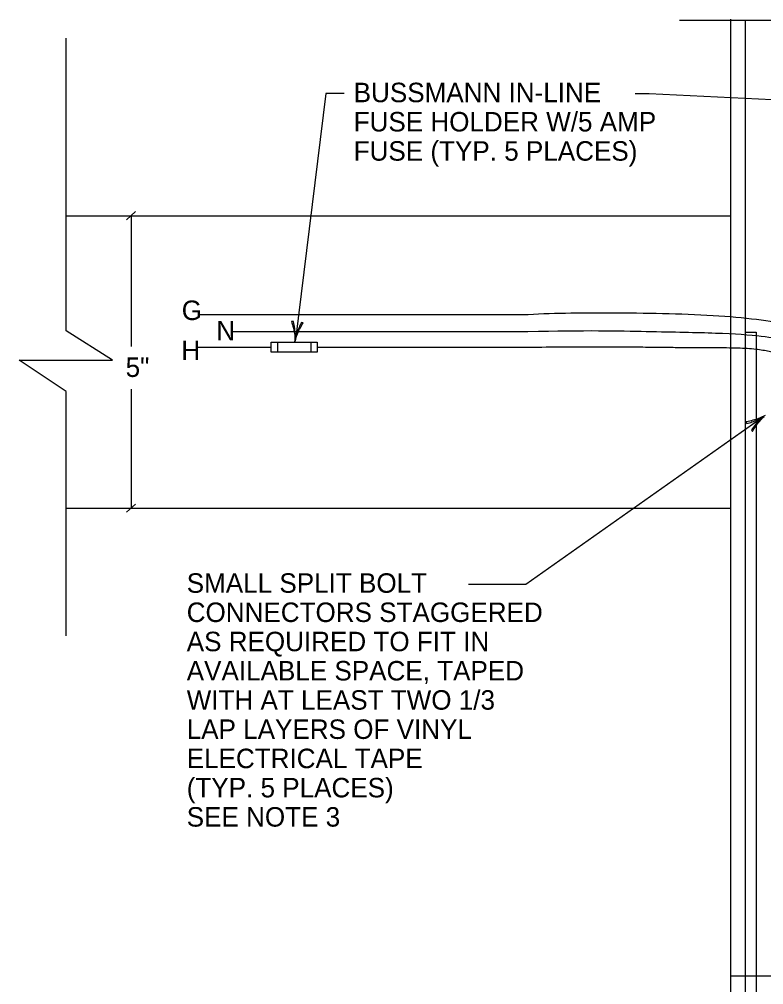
# Model space of a CAD drawing. Extents: x 10099 to 10284, y 10005 to 10185.
# Drawn here: x 10123.06 to 10148.54, y 10150.04 to 10183.07 of the extents above; entities that cross this region are included whole.
import ezdxf

# ---------------------------------------------------------------- set-up
doc = ezdxf.new("R2010")
doc.units = 0
doc.layers.add('Level 46', color=7, linetype='Continuous')
doc.layers.add('Level 5', color=7, linetype='Continuous')

msp = doc.modelspace()

# ---------------------------------------------------------------- linework, layer by layer
at = {"layer": 'Level 46'}
for p, q in [((10150.41, 10183.028), (10145.651, 10183.028)), ((10147.404, 10183.071), (10147.404, 10122.109)), ((10147.904, 10183.049), (10147.904, 10120.1)), ((10124.661, 10172.41), (10124.661, 10182.42)), ((10133.557, 10180.531), (10132.513, 10172.1)), ((10134.175, 10180.531), (10133.557, 10180.531)), ((10144.144, 10180.535), (10144.614, 10180.535)), ((10144.614, 10180.535), (10149.762, 10180.283)), ((10124.661, 10176.35), (10147.404, 10176.35)), ((10127.042, 10176.49), (10126.734, 10176.212)), ((10126.888, 10176.353), (10126.888, 10171.872)), ((10126.248, 10171.409), (10124.661, 10172.41)), ((10147.904, 10172.363), (10148.279, 10172.363)), ((10148.279, 10172.363), (10148.279, 10132.35)), ((10124.661, 10170.341), (10123.061, 10171.409)), ((10123.061, 10171.409), (10126.248, 10171.409)), ((10124.661, 10161.98), (10124.661, 10170.341)), ((10126.888, 10170.416), (10126.888, 10166.35)), ((10140.399, 10163.748), (10148.537, 10169.495)), ((10124.661, 10166.35), (10147.404, 10166.35)), ((10127.042, 10166.487), (10126.734, 10166.209)), ((10138.438, 10163.748), (10140.399, 10163.748)), ((10147.404, 10150.35), (10155.404, 10150.35))]:
    msp.add_line(p, q, dxfattribs=at)
for points in [[(10132.496, 10172.042), (10132.513, 10172.1), (10132.529, 10172.156), (10132.55, 10172.23), (10132.581, 10172.305), (10132.607, 10172.369), (10132.63, 10172.425), (10132.654, 10172.47), (10132.681, 10172.52), (10132.706, 10172.566), (10132.732, 10172.614), (10132.758, 10172.655), (10132.779, 10172.687), (10132.713, 10172.696), (10132.691, 10172.655), (10132.671, 10172.615), (10132.653, 10172.572), (10132.635, 10172.53), (10132.613, 10172.477), (10132.595, 10172.436), (10132.577, 10172.378), (10132.561, 10172.328), (10132.544, 10172.272), (10132.531, 10172.219), (10132.521, 10172.171), (10132.513, 10172.132), (10132.505, 10172.091), (10132.496, 10172.042), (10132.5, 10172.105), (10132.502, 10172.167), (10132.506, 10172.249), (10132.502, 10172.324), (10132.499, 10172.379), (10132.496, 10172.437), (10132.489, 10172.492), (10132.478, 10172.563), (10132.47, 10172.614), (10132.459, 10172.666), (10132.445, 10172.729), (10132.377, 10172.737), (10132.394, 10172.69), (10132.415, 10172.622), (10132.427, 10172.571), (10132.444, 10172.504), (10132.46, 10172.438), (10132.468, 10172.382), (10132.478, 10172.313), (10132.486, 10172.263), (10132.489, 10172.208), (10132.491, 10172.154), (10132.494, 10172.098), (10132.496, 10172.042)], [(10148.591, 10169.521), (10148.537, 10169.495), (10148.484, 10169.469), (10148.415, 10169.435), (10148.339, 10169.407), (10148.274, 10169.384), (10148.217, 10169.363), (10148.167, 10169.351), (10148.113, 10169.337), (10148.062, 10169.324), (10148.009, 10169.311), (10147.961, 10169.303), (10147.923, 10169.297), (10147.961, 10169.242), (10148.006, 10169.254), (10148.049, 10169.266), (10148.093, 10169.281), (10148.136, 10169.296), (10148.19, 10169.316), (10148.233, 10169.33), (10148.288, 10169.355), (10148.335, 10169.377), (10148.388, 10169.403), (10148.436, 10169.428), (10148.478, 10169.453), (10148.513, 10169.474), (10148.548, 10169.495)], [(10148.541, 10169.482), (10148.494, 10169.442), (10148.431, 10169.39), (10148.378, 10169.337), (10148.339, 10169.297), (10148.298, 10169.256), (10148.262, 10169.213), (10148.217, 10169.157), (10148.185, 10169.118), (10148.153, 10169.074), (10148.117, 10169.022), (10148.156, 10168.966), (10148.18, 10169.01), (10148.216, 10169.072), (10148.246, 10169.115), (10148.284, 10169.172), (10148.322, 10169.229), (10148.358, 10169.272), (10148.402, 10169.326), (10148.434, 10169.365), (10148.472, 10169.405), (10148.511, 10169.443), (10148.551, 10169.482)]]:
    msp.add_lwpolyline(points, dxfattribs=at)
at = {"layer": 'Level 5'}
for p, q in [((10131.893, 10172.029), (10131.893, 10171.685)), ((10133.034, 10172.029), (10133.034, 10171.685))]:
    msp.add_line(p, q, dxfattribs=at)
msp.add_lwpolyline([(10133.255, 10172.028), (10133.255, 10171.685), (10131.682, 10171.685), (10131.682, 10172.028)], close=True, dxfattribs=at)
for points, degree in [([(10140.481, 10172.963), (10135.84, 10172.963), (10132.143, 10172.963), (10129.173, 10172.963)], 2), ([(10149.569, 10172.575), (10148.938, 10172.724), (10147.205, 10172.964), (10143.405, 10173.036), (10141.417, 10173.018), (10140.481, 10172.963)], 3), ([(10140.463, 10172.375), (10136.436, 10172.375), (10133.112, 10172.375), (10130.356, 10172.375)], 2), ([(10149.925, 10171.499), (10149.835, 10171.61), (10149.631, 10171.85), (10149.333, 10172.083), (10148.593, 10172.229), (10147.014, 10172.339), (10144.694, 10172.375), (10142.452, 10172.43), (10140.463, 10172.375)], 3), ([(10131.677, 10171.845), (10130.727, 10171.845), (10129.88, 10171.845), (10129.114, 10171.845)], 2), ([(10140.522, 10171.845), (10137.605, 10171.845), (10135.234, 10171.845), (10133.259, 10171.845)], 2), ([(10149.547, 10170.999), (10149.411, 10171.315), (10149.333, 10171.479), (10148.944, 10171.68), (10147.969, 10171.827), (10146.253, 10171.827), (10143.232, 10171.863), (10140.522, 10171.845)], 2)]:
    msp.add_open_spline(points, degree=degree, dxfattribs=at)

# ---------------------------------------------------------------- texts
at = {"layer": 'Level 46'}
for s, height, p in [('BUSSMANN IN-LINE', 0.66667, (10134.505, 10180.234)), ('FUSE HOLDER W/5 AMP', 0.66667, (10134.505, 10179.234)), ('FUSE (TYP. 5 PLACES)', 0.66667, (10134.505, 10178.234)), ('G', 0.667, (10128.62, 10172.782)), ('N', 0.667, (10129.802, 10172.083)), ('H', 0.667, (10128.605, 10171.41)), ('5"', 0.6667, (10126.701, 10170.835)), ('SMALL SPLIT BOLT', 0.66667, (10128.791, 10163.451)), ('CONNECTORS STAGGERED', 0.66667, (10128.791, 10162.451)), ('AS REQUIRED TO FIT IN', 0.66667, (10128.791, 10161.451)), ('AVAILABLE SPACE, TAPED', 0.66667, (10128.791, 10160.451)), ('WITH AT LEAST TWO 1/3', 0.66667, (10128.791, 10159.451)), ('LAP LAYERS OF VINYL', 0.66667, (10128.791, 10158.451)), ('ELECTRICAL TAPE', 0.66667, (10128.791, 10157.451)), ('(TYP. 5 PLACES)', 0.66667, (10128.791, 10156.451)), ('SEE NOTE 3', 0.6667, (10128.791, 10155.451))]:
    msp.add_text(s, height=height, dxfattribs=at).set_placement(p)

doc.saveas('drawing.dxf')
